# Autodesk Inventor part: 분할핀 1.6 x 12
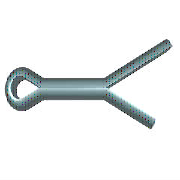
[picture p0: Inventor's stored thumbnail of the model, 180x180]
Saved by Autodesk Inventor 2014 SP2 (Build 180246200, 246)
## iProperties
IsCustomPart: 1
Created: 2012-02
Part Number: 분할핀 1.6 x 12
Material: 강철, 연강
Description: 분할 핀
Document SubType Name: Modeling
Standard: KS B 1321
Designer: mduedu
Standards Organization: KS
Language: ko-KR
Size Designation: 1.6 x  12
Categories: <MemberInstance><Categories><Category DisplayName="조임쇠" InternalName="e4da775c-781d-43d5-af7c-5136215cf5a6" Mnemonic="FSTN"><Category DisplayName="핀" InternalNa
Density: 1 g/cm^3
Appearance: 강철
Author: mduedu
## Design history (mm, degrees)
sketch "스케치1"
  geometry: L1 (0, 0.7)-(7, 0.7); L2 (0, -0.7)-(7, -0.7); L3 (7, 0.7)-(12, 2.616); L4 (12, 2.616)-(12.234, 2.005); L5 (12.234, 2.005)-(7, 0); L6 (7, 0)-(14.734, -2.963); L7 (14.734, -2.963)-(14.5, -3.573); L8 (14.5, -3.573)-(7, -0.7); L9 (0, 0)-(-1.528, -0.645); L10 (0, 0)-(-1.528, 0.645); L11 (0, 0.7)-(0, -0.7); L12 (0, 0.7)-(-1.204, 1.267); L13 (0, -0.7)-(-1.204, -1.267); L14 (-3.2, 0)-(7, 0); L15 (7, 0.7)-(7, -0.7); A1 r 1.4 centre (-1.8, 0) between (-1.204, 1.267) and (-1.204, -1.267); A2 r 0.7 centre (-1.8, 0) between (-1.528, 0.645) and (-1.528, -0.645); 1 further point
  constraints: 30 end point, 5 point on circle, 4 parallel, 4 perpendicular, 4 point on line, 4 tangent, 2 centre point, 2 midpoint, 1 coincident, 1 horizontal
  dimensions: "d0" = 7 distance of L1.start L1.end (= MSIAB); "d1" = 12 horizontal distance of L1.start L3.end (= SNLG); "d2" = 159.037 deg angle of L1 L3; "d3" = 159.037 deg angle of L2 L8; "d4" = 2.5 horizontal distance of L3.end L7.end (= LGDIF); "d5" = 0.7 radius of A2 (= -0.5 x SNND1 + 0.5 x KBR); "d6" = 1.4 radius of A1 (= 0.5 x KBR); "d7" = 0.7 distance from line of L1 L9.start (= 0.5 x SNND1); "d8" = 0.7 distance between parallel lines of L2 L14 (= 0.5 x SNND1); "d9" = 1.8 distance from line of L11 A1.centre (= KOL - 0.5 x KBR)
extrude "본체" new body sketch "스케치1" stored distance "d10" = 1.4 (= SNND1); taper "d11" = 0 deg
workaxis "Work Axis1"
workplane "Work Plane1"
workplane "Work Plane3"
body "Solid1"
fillet "모깎기" dims "d12" = 0.49 (= 0.35 x SNND1)
other parameters: "SNND" = 1.6 [user parameter], "SNLG" = 12 [user parameter; used in 1 equation term], "SNND1" = 1.4 [user parameter; used in 5 equation terms], "KBR" = 2.8 [user parameter; used in 3 equation terms], "KOL" = 3.2 [user parameter; used in 1 equation term], "LGDIF" = 2.5 [user parameter; used in 1 equation term], "MSIAB" = 7 [user parameter; used in 1 equation term], "d15" = 0, "d16" = 0, "d17" = 0, "NNDMAX" = 7 [user parameter], "DSH" = 6 [user parameter], "NNDMIN" = 5.5 [user parameter]
